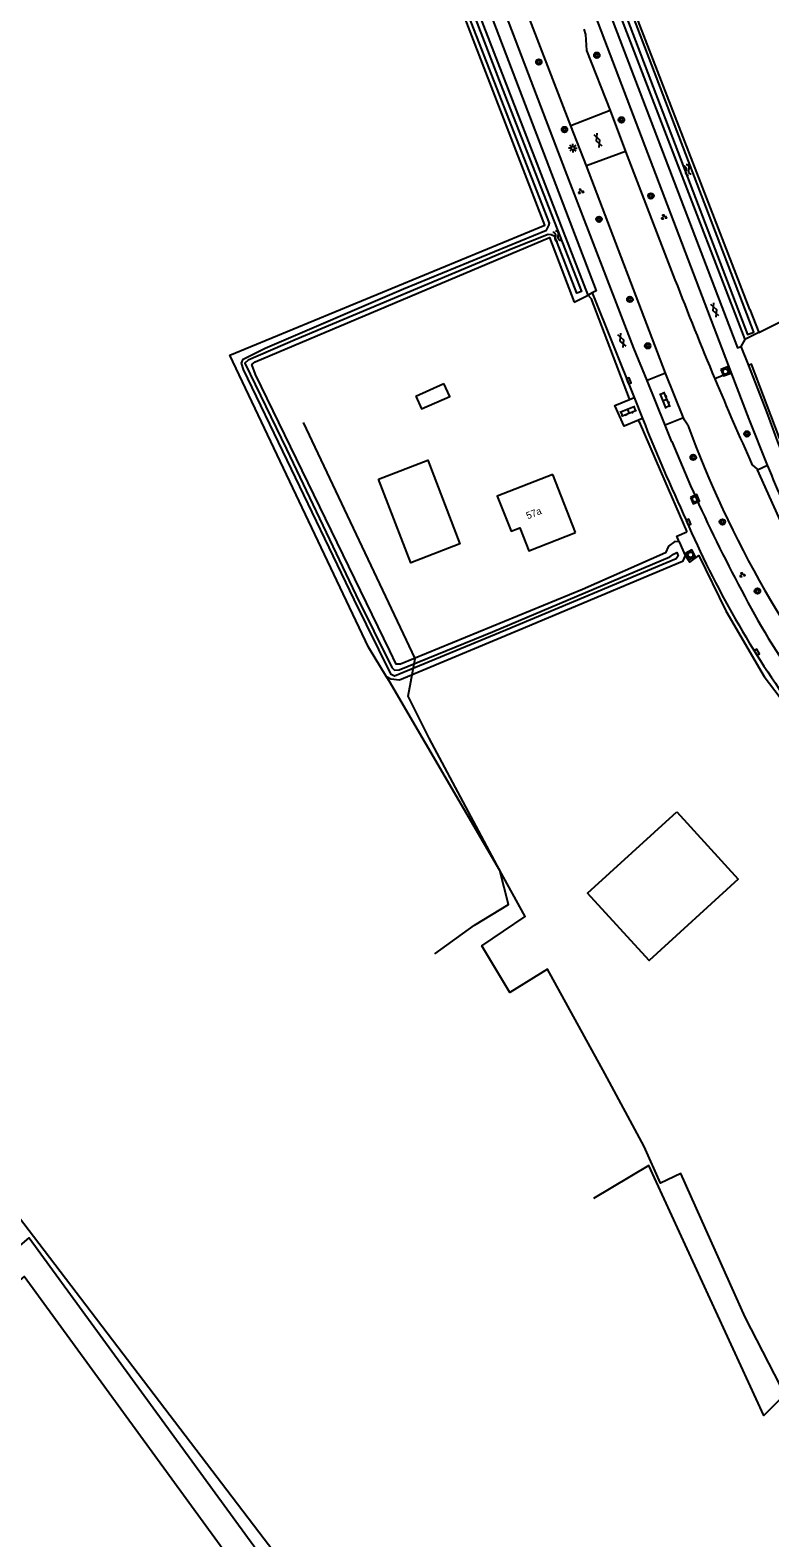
# Model space of a CAD drawing. Extents: x 134297 to 137000, y 403500 to 406000.
# Drawn here: x 136234.5 to 136340, y 404106.3 to 404321.6 of the extents above; entities that cross this region are included whole.
import ezdxf

# ---------------------------------------------------------------- set-up
doc = ezdxf.new("R2010")
doc.units = 0
for name, color, linetype in [('gg-afsc-draadraster', 7, 'Continuous'), ('gg-afsc-erfafscheiding', 7, 'Continuous'), ('gg-afsc-lijn draadraster', 7, 'Continuous'), ('gg-anno-huisnummerreeks BGT', 7, 'Continuous'), ('gg-bbg-gedigitaliseerde bebouwing', 7, 'Continuous'), ('gg-bbg-gedigitaliseerde bijgebouw', 7, 'Continuous'), ('gg-bbg-hoofdgebouw', 7, 'Continuous'), ('gg-knt-bronhoudergrens', 7, 'Continuous'), ('gg-knt-onverhard', 7, 'Continuous'), ('gg-knt-verharding', 7, 'Continuous'), ('gg-kntw-bovenkant insteek waterloop', 7, 'Continuous'), ('gg-kntw-waterlijn', 7, 'Continuous'), ('gt-grn-groengrens', 7, 'Continuous'), ('gt-grn-vlakafsluiter', 7, 'Continuous'), ('gt-symb-boom', 7, 'Continuous'), ('gt-symb-gesloten verharding', 7, 'Continuous'), ('gt-symb-groenvak', 7, 'Continuous'), ('gt-symb-klinker verharding', 7, 'Continuous'), ('gt-symb-kolk', 7, 'Continuous'), ('gt-symb-lichtmast', 7, 'Continuous'), ('gt-symb-rioolschacht', 7, 'Continuous'), ('gt-symb-watersymbool', 7, 'Continuous')]:
    doc.layers.add(name, color=color, linetype=linetype)

# ---------------------------------------------------------------- blocks, each defined once
blk = doc.blocks.new('gt0-RS')
at = {"layer": 'gt-symb-rioolschacht'}
blk.add_lwpolyline([(-0.5, -0.5), (0.5, -0.5), (0.5, 0.5), (-0.5, 0.5)], close=True, dxfattribs=at)
blk.add_circle((0, 0), 0.375, dxfattribs=at)
blk = doc.blocks.new('gt0-BOOM')
at = {"layer": 'gt-symb-boom'}
for radius in [0.4, 0.2]:
    blk.add_circle((0, 0), radius, dxfattribs=at)
blk = doc.blocks.new('gt0-GESVH1')
at = {"layer": 'gt-symb-gesloten verharding'}
for p, q in [((-0.99, -0.26), (0.01, 0.24)), ((0.01, -0.26), (-0.99, 0.24)), ((0.01, 0.24), (1.01, -0.26)), ((1.01, 0.24), (0.01, -0.26))]:
    blk.add_line(p, q, dxfattribs=at)
blk = doc.blocks.new('gt0-KOLK')
at = {"layer": 'gt-symb-kolk'}
blk.add_lwpolyline([(0, 0), (0.38, 0), (0.38, 0.4), (-0.38, 0.4), (-0.38, 0), (0, 0)], dxfattribs=at)
blk = doc.blocks.new('gt0-KL1')
at = {"layer": 'gt-symb-klinker verharding'}
for p, q in [((-1.15, 0.3), (1.15, 0.3)), ((-1, -0.3), (-1, 0.3)), ((-0.5, 0.3), (-0.5, 0.45)), ((0, -0.3), (0, 0.3)), ((0.5, 0.3), (0.5, 0.45)), ((1, -0.3), (1, 0.3)), ((-1.15, -0.3), (1.15, -0.3)), ((-0.5, -0.45), (-0.5, -0.3)), ((0.5, -0.45), (0.5, -0.3))]:
    blk.add_line(p, q, dxfattribs=at)
blk = doc.blocks.new('gt0-GRVAK')
at = {"layer": 'gt-symb-groenvak'}
for p, q in [((-0.11, 0.19), (-0.23, 0.24)), ((-0.18, 0.15), (0.09, 0.15)), ((-0.09, 0.21), (-0.16, 0.32)), ((-0.05, 0.21), (-0.05, 0.39)), ((0, 0.21), (0.06, 0.32)), ((0.01, 0.19), (0.13, 0.24)), ((0.26, -0.05), (0.2, 0.06)), ((0.3, -0.05), (0.3, 0.13)), ((0.35, -0.05), (0.41, 0.06)), ((-0.24, -0.23), (-0.36, -0.18)), ((-0.32, -0.26), (-0.05, -0.26)), ((-0.23, -0.21), (-0.29, -0.09)), ((-0.18, -0.2), (-0.18, -0.02)), ((-0.14, -0.21), (-0.07, -0.09)), ((-0.12, -0.23), (0, -0.18)), ((0.24, -0.07), (0.12, -0.02)), ((0.17, -0.11), (0.44, -0.11)), ((0.37, -0.07), (0.49, -0.02))]:
    blk.add_line(p, q, dxfattribs=at)
blk = doc.blocks.new('gt0-WA')
at = {"layer": 'gt-symb-watersymbool'}
for centre, start, end in [((-0.32, 0.02), 28.0725, 151.9275), ((0.43, 0.42), 208.0725, 331.9275), ((-0.32, -0.43), 28.0725, 151.9275), ((0.43, -0.03), 208.0725, 331.9275)]:
    blk.add_arc(centre, 0.425, start, end, dxfattribs=at)
blk = doc.blocks.new('gt0-LMAST')
at = {"layer": 'gt-symb-lichtmast'}
for p, q in [((-0.18, 0.17), (-0.45, 0.44)), ((-0.01, 0.25), (-0.01, 0.62)), ((0.17, 0.17), (0.44, 0.44)), ((-0.26, 0), (-0.63, 0)), ((-0.18, -0.18), (-0.45, -0.45)), ((-0.01, -0.25), (-0.01, -0.63)), ((0.44, -0.45), (0.17, -0.18)), ((0.24, 0), (0.62, 0))]:
    blk.add_line(p, q, dxfattribs=at)
blk.add_circle((-0.01, 0), 0.25, dxfattribs=at)

msp = doc.modelspace()

# ---------------------------------------------------------------- linework, layer by layer
at = {"layer": 'gg-afsc-draadraster'}
for points in [[(136130.86, 404369.52), (136091.04, 404340.78), (136143.53, 404270.85), (136213.44, 404177.65), (136238.01, 404145.41)], [(136238.01, 404145.41), (136291.68, 404074.98), (136312.51, 404046.8), (136326.97, 404027.77), (136332.85, 404021.61), (136355.98, 404056.53), (136424.58, 404064.5), (136423.36, 404080.36), (136423.83, 404085.94), (136425.22, 404091.86), (136430.27, 404101.61), (136454.12, 404143.13)]]:
    msp.add_lwpolyline(points, dxfattribs=at)
at = {"layer": 'gg-afsc-erfafscheiding'}
msp.add_line((136314.49, 404283.32), (136319.96, 404268.95), dxfattribs=at)
msp.add_lwpolyline([(136321.38, 404265.66), (136324.44, 404258.64), (136328.18, 404249.96)], dxfattribs=at)
at = {"layer": 'gg-afsc-lijn draadraster'}
for points in [[(136130.86, 404369.52), (136091.04, 404340.78), (136143.53, 404270.85), (136213.44, 404177.65), (136238.01, 404145.41)], [(136292.22, 404189.71), (136297.88, 404193.83), (136302.73, 404196.74), (136301.51, 404201.61), (136291.42, 404220.49), (136288.45, 404226.53), (136289.43, 404231.89), (136273.48, 404265.6)], [(136393.29, 404178.34), (136339.17, 404123.79), (136322.77, 404159.51), (136314.88, 404154.81)], [(136238.01, 404145.41), (136291.68, 404074.98), (136312.51, 404046.8), (136326.97, 404027.77), (136332.85, 404021.61), (136355.98, 404056.53), (136424.58, 404064.5), (136423.36, 404080.36), (136423.83, 404085.94), (136425.22, 404091.86), (136430.27, 404101.61), (136454.12, 404143.13)]]:
    msp.add_lwpolyline(points, dxfattribs=at)
at = {"layer": 'gg-bbg-gedigitaliseerde bebouwing'}
msp.add_lwpolyline([(136309.05, 404258.17), (136301.14, 404255.06), (136303.11, 404250.06), (136304.36, 404250.56), (136305.65, 404247.26), (136312.31, 404249.87)], dxfattribs=at)
at = {"layer": 'gg-bbg-gedigitaliseerde bijgebouw'}
msp.add_line((136289.51, 404269.35), (136293.53, 404271.14), dxfattribs=at)
for points in [[(136289.51, 404269.35), (136290.33, 404267.52), (136294.35, 404269.31), (136293.53, 404271.14)], [(136284.19, 404257.48), (136291.21, 404260.18), (136295.81, 404248.25), (136288.79, 404245.54), (136284.19, 404257.48)]]:
    msp.add_lwpolyline(points, dxfattribs=at)
at = {"layer": 'gg-bbg-hoofdgebouw'}
msp.add_line((136312.31, 404249.87), (136309.05, 404258.17), dxfattribs=at)
msp.add_lwpolyline([(136326.73, 404209.99), (136335.52, 404200.38), (136322.82, 404188.77), (136314.03, 404198.38), (136326.73, 404209.99)], dxfattribs=at)
at = {"layer": 'gg-knt-bronhoudergrens'}
for points in [[(136338.46, 404278.41), (136358.52, 404288.51), (136359, 404287.55), (136384.88, 404301.31), (136382.53, 404305.72)], [(136393.29, 404178.34), (136342.86, 404127.51), (136341.55, 404128.06), (136336.52, 404137.85), (136327.33, 404158.36), (136324.42, 404156.97), (136322.1, 404162.19), (136316.48, 404172.64), (136308.28, 404187.53), (136302.92, 404184.22), (136298.95, 404190.84), (136305.1, 404195.07), (136301.51, 404201.61), (136285.75, 404228.6), (136285.35, 404229.26)]]:
    msp.add_lwpolyline(points, dxfattribs=at)
at = {"layer": 'gg-knt-onverhard'}
for points in [[(135992.34, 403933.8), (136026.33, 403963.71), (136082.98, 404013.55), (136148.58, 404073.96), (136176.66, 404099.82), (136234.38, 404149.17), (136287.06, 404076.9)], [(136284.71, 404073.5), (136233.64, 404143.65), (136214.96, 404127.77), (136166.9, 404085.37)]]:
    msp.add_lwpolyline(points, dxfattribs=at)
at = {"layer": 'gg-knt-verharding'}
for p, q in [((136311.62, 404307.94), (136288.6, 404367.74)), ((136334.51, 404272.78), (136315.19, 404323.54)), ((136317.22, 404310.11), (136311.62, 404307.94)), ((136317.22, 404310.11), (136319.42, 404304.29)), ((136313.86, 404302.24), (136311.62, 404307.94)), ((136319.42, 404304.29), (136313.86, 404302.24)), ((136319.42, 404304.29), (136326.48, 404285.95)), ((136325.12, 404272.61), (136313.86, 404302.24)), ((136314.68, 404284.1), (136320.65, 404269.14)), ((136335.9, 404276.42), (136336.96, 404273.72)), ((136325.12, 404272.61), (136322.5, 404271.57)), ((136327.69, 404266.25), (136325.12, 404272.61)), ((136325.08, 404265.2), (136322.5, 404271.57)), ((136319.99, 404268.87), (136320.65, 404269.14)), ((136320.65, 404269.14), (136321.85, 404266.15)), ((136321.85, 404266.15), (136321.27, 404265.91)), ((136327.69, 404266.25), (136325.08, 404265.2)), ((136326.05, 404262.84), (136325.08, 404265.2)), ((136338.24, 404258.84), (136339.67, 404259.49)), ((136339.71, 404259.4), (136339.67, 404259.49)), ((136343, 404248.25), (136338.24, 404258.84))]:
    msp.add_line(p, q, dxfattribs=at)
for points in [[(136284.1, 404366.1), (136315.26, 404284.37), (136314.68, 404284.1)], [(136322.5, 404271.57), (136320.63, 404276.19), (136310.87, 404301.5), (136285.99, 404366.78)], [(136317.01, 404324.46), (136335.39, 404276.23), (136335.9, 404276.42)], [(136313.49, 404321.75), (136313.73, 404320.97), (136313.85, 404318.69), (136317.22, 404310.11)], [(136339.67, 404259.49), (136337.06, 404266.06), (136334.51, 404272.78)], [(136336.96, 404273.72), (136339.56, 404267.09), (136341.11, 404262.84), (136342.8, 404258.65)], [(136321.27, 404265.91), (136319.26, 404265.05), (136317.91, 404268.02), (136319.99, 404268.87)], [(136328.34, 404265.18), (136327.85, 404265.93), (136327.69, 404266.25)], [(136337.51, 404259.51), (136338.21, 404258.92), (136338.24, 404258.84)]]:
    msp.add_lwpolyline(points, dxfattribs=at)
for centre, radius, start, end in [((136833, 404481.72), 543.03, 201.1312, 202.7408), ((136832.23, 404481.34), 542.18, 202.7357, 204.1513), ((136574.55, 404366.05), 271.73, 201.5715, 204.901), ((136471.17, 404317.36), 152.07, 200.066, 219.6889), ((136531.38, 404345.9), 221.49, 202.0225, 210.1102), ((136457.06, 404305.71), 126.16, 201.5347, 206.7558), ((136456.89, 404306.95), 140.19, 203.237, 216.1199), ((136441.51, 404297.69), 119.62, 211.7323, 222.5531)]:
    msp.add_arc(centre, radius, start, end, dxfattribs=at)
at = {"layer": 'gg-kntw-bovenkant insteek waterloop'}
for p, q in [((136318.17, 404325.04), (136336.47, 404277.42)), ((136337.18, 404281.72), (136320.9, 404323.79)), ((136312.11, 404282.78), (136314.09, 404283.75)), ((136337.18, 404281.72), (136338.46, 404278.41)), ((136338.46, 404278.41), (136336.47, 404277.42)), ((136327.07, 404248.56), (136327.94, 404246.57))]:
    msp.add_line(p, q, dxfattribs=at)
for points in [[(136285.35, 404229.26), (136282.77, 404233.5), (136262.99, 404275.17), (136307.91, 404293.73), (136281.27, 404363.02)], [(136314.09, 404283.75), (136283.2, 404363.67), (136281.27, 404363.02)], [(136327.07, 404248.56), (136326.48, 404248.61), (136325.55, 404247.91), (136325.15, 404246.95), (136313.31, 404241.73), (136287.32, 404231.08), (136286.72, 404231.08), (136285.83, 404232.96), (136266.65, 404272.42), (136266.12, 404273.84), (136266.58, 404274.24), (136308.57, 404292), (136312.11, 404282.78)], [(136327.94, 404246.57), (136327.57, 404245.73), (136304.25, 404235.94), (136287.19, 404228.79), (136285.96, 404228.93), (136285.35, 404229.26)]]:
    msp.add_lwpolyline(points, dxfattribs=at)
at = {"layer": 'gg-kntw-waterlijn'}
for points in [[(136289.59, 404345.23), (136301.88, 404313.17), (136313.13, 404284.3), (136312.48, 404284.05), (136309.33, 404292.14), (136308.83, 404292.39), (136308.4, 404292.44), (136303.36, 404290.41), (136272.32, 404277.39), (136265.62, 404274.5), (136265.15, 404274.05), (136271.05, 404261.75), (136280.94, 404240.96), (136286.08, 404230.58), (136286.5, 404230.21), (136287.16, 404230.27), (136300.47, 404235.69), (136325.77, 404246.41), (136326.29, 404246.8), (136326.77, 404247.01), (136326.93, 404246.54), (136326.64, 404246.11), (136302.35, 404235.93), (136286.47, 404229.37), (136286, 404229.6), (136280.73, 404240.32), (136271.15, 404260.22)], [(136271.15, 404260.22), (136264.94, 404273.13), (136264.65, 404274.03), (136264.91, 404274.61), (136268.03, 404276.17), (136287.77, 404284.66), (136308.18, 404293.02), (136308.51, 404293.69), (136308.58, 404294.05), (136295.64, 404327.28)], [(136319.1, 404324.67), (136336.84, 404278.13), (136337.72, 404278.47), (136319.95, 404325.08), (136319.1, 404324.67)]]:
    msp.add_lwpolyline(points, dxfattribs=at)
at = {"layer": 'gt-grn-groengrens'}
for p, q in [((136314.68, 404284.1), (136314.09, 404283.75)), ((136314.49, 404283.32), (136314.09, 404283.75)), ((136336.47, 404277.42), (136335.9, 404276.42)), ((136334.51, 404272.78), (136332.18, 404271.8)), ((136319.96, 404268.95), (136319.99, 404268.87)), ((136321.38, 404265.66), (136321.27, 404265.91))]:
    msp.add_line(p, q, dxfattribs=at)
for points in [[(136343.51, 404258.97), (136341.36, 404263.49), (136337.42, 404273.89), (136336.96, 404273.72)], [(136327.94, 404246.57), (136328.59, 404245.65), (136329.89, 404246.57), (136333.76, 404238.7), (136339.23, 404229.3), (136347.1, 404218.94), (136342.8, 404214.79), (136348.37, 404208.72)]]:
    msp.add_lwpolyline(points, dxfattribs=at)
at = {"layer": 'gt-grn-vlakafsluiter'}
msp.add_lwpolyline([(136327.07, 404248.56), (136326.74, 404249.33), (136328.18, 404249.96)], dxfattribs=at)

# ---------------------------------------------------------------- block references
at = {"layer": 'gt-symb-boom'}
for p in [(136315.34, 404318.01), (136307.07, 404317.05), (136318.85, 404308.78), (136310.73, 404307.4), (136323.06, 404297.92), (136315.65, 404294.59), (136320.06, 404283.15), (136322.6, 404276.52), (136336.76, 404263.95), (136329.09, 404260.6), (136333.25, 404251.38), (136338.25, 404241.52)]:
    msp.add_blockref('gt0-BOOM', p, dxfattribs=at)
at = {"layer": 'gt-symb-gesloten verharding'}
for p, rotation in [((136315.51, 404305.87), -68.53893641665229), ((136332.15, 404281.62), 112.02484593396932), ((136318.9, 404277.28), 112.02484593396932)]:
    msp.add_blockref('gt0-GESVH1', p, dxfattribs=dict(at, rotation=rotation))
at = {"layer": 'gt-symb-groenvak'}
for p in [(136313.03, 404298.59), (136324.9, 404294.93), (136336.08, 404243.84)]:
    msp.add_blockref('gt0-GRVAK', p, dxfattribs=at)
at = {"layer": 'gt-symb-klinker verharding'}
for p, rotation in [((136325.08, 404268.77), 112.5141126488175), ((136319.82, 404267.14), -157.7196289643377)]:
    msp.add_blockref('gt0-KL1', p, dxfattribs=dict(at, rotation=rotation))
at = {"layer": 'gt-symb-kolk'}
for p, rotation in [((136319.73, 404271.44), -68.230498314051), ((136328.24, 404251.26), -66.97450799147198), ((136338, 404232.67), -58.99693247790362)]:
    msp.add_blockref('gt0-KOLK', p, dxfattribs=dict(at, rotation=rotation))
at = {"layer": 'gt-symb-lichtmast'}
msp.add_blockref('gt0-LMAST', (136311.93, 404304.75), dxfattribs=at)
at = {"layer": 'gt-symb-rioolschacht'}
for p, rotation in [((136333.69, 404272.87), -68.23049831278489), ((136329.34, 404254.62), -66.97450799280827), ((136328.71, 404246.7), 28.575680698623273)]:
    msp.add_blockref('gt0-RS', p, dxfattribs=dict(at, rotation=rotation))
at = {"layer": 'gt-symb-watersymbool'}
for p, rotation in [((136328.28, 404301.57), 118.99897714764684), ((136309.65, 404292.11), 118.99897714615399)]:
    msp.add_blockref('gt0-WA', p, dxfattribs=dict(at, rotation=rotation))

# ---------------------------------------------------------------- texts
at = {"layer": 'gg-anno-huisnummerreeks BGT'}
msp.add_text('57a', height=1, rotation=21.5, dxfattribs=at).set_placement((136305.49, 404251.75))

doc.saveas('drawing.dxf')
